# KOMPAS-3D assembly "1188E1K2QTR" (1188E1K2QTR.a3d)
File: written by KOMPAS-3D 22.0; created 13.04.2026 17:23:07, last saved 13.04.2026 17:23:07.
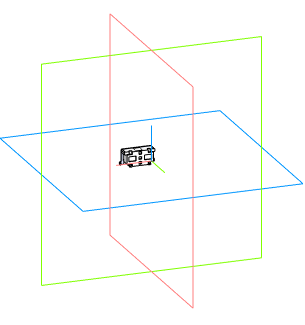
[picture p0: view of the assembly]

Document properties: Автор: Andrey; Полное имя файла: C:\Users\User1\Documents\1188E1K2QTR.a3d

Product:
- Component [detail]: TL3330AF130QG  | qty 1  | source file: TL3330AF130QG.m3d
- Part/product: 1188E1K2QTR
    Комментарий: 1188E1K2QTR

Referenced files in C:\Users\User1\Documents\: TL3330AF130QG.m3d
